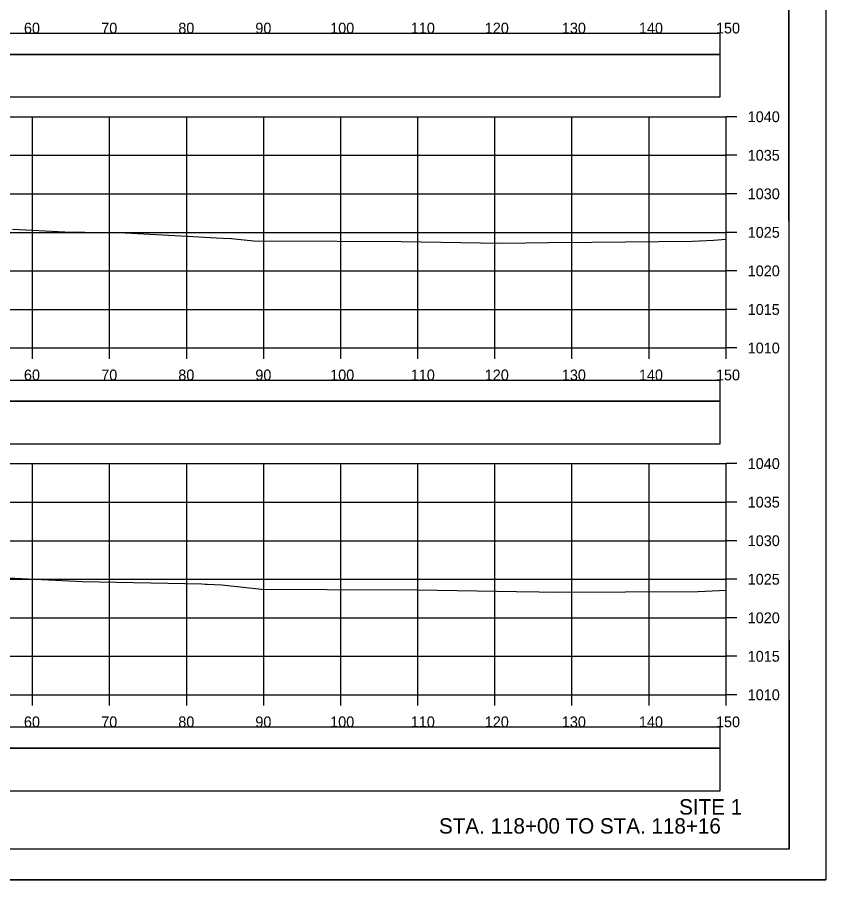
# Model space of a CAD drawing. Extents: x 1370565 to 1374448, y 301010 to 304637.
# Drawn here: x 1370793 to 1370898, y 302930.5 to 303042.4 of the extents above; entities that cross this region are included whole.
import ezdxf

# ---------------------------------------------------------------- set-up
doc = ezdxf.new("R2010")
doc.units = 0
for name, color, linetype in [('R_Axis', 7, 'Continuous'), ('R_Axis Annot', 7, 'Continuous'), ('R_Border', 7, 'Continuous'), ('R_Draft', 7, 'Continuous'), ('R_Drive', 7, 'Continuous'), ('R_Exist Surface', 7, 'Continuous'), ('R_Grid', 7, 'Continuous'), ('R_No Plot', 7, 'Continuous')]:
    doc.layers.add(name, color=color, linetype=linetype)

msp = doc.modelspace()

# ---------------------------------------------------------------- linework, layer by layer
at = {"layer": 'R_Axis'}
for p, q in [((1370885.03, 302999.52), (1370885.03, 303029.52)), ((1370886.43, 303029.52), (1370885.03, 303029.52)), ((1370886.43, 303024.52), (1370885.03, 303024.52)), ((1370886.43, 303019.52), (1370885.03, 303019.52)), ((1370886.43, 303014.52), (1370885.03, 303014.52)), ((1370886.43, 303009.52), (1370885.03, 303009.52)), ((1370886.43, 303004.52), (1370885.03, 303004.52)), ((1370585.03, 302999.52), (1370885.03, 302999.52)), ((1370795.03, 302998.12), (1370795.03, 302999.52)), ((1370805.03, 302998.12), (1370805.03, 302999.52)), ((1370815.03, 302998.12), (1370815.03, 302999.52)), ((1370825.03, 302998.12), (1370825.03, 302999.52)), ((1370835.03, 302998.12), (1370835.03, 302999.52)), ((1370845.03, 302998.12), (1370845.03, 302999.52)), ((1370855.03, 302998.12), (1370855.03, 302999.52)), ((1370865.03, 302998.12), (1370865.03, 302999.52)), ((1370875.03, 302998.12), (1370875.03, 302999.52)), ((1370885.03, 302998.12), (1370885.03, 302999.52)), ((1370886.43, 302999.52), (1370885.03, 302999.52)), ((1370885.03, 302954.52), (1370885.03, 302984.52)), ((1370886.43, 302984.52), (1370885.03, 302984.52)), ((1370886.43, 302979.52), (1370885.03, 302979.52)), ((1370886.43, 302974.52), (1370885.03, 302974.52)), ((1370886.43, 302969.52), (1370885.03, 302969.52)), ((1370886.43, 302964.52), (1370885.03, 302964.52)), ((1370886.43, 302959.52), (1370885.03, 302959.52)), ((1370585.03, 302954.52), (1370885.03, 302954.52)), ((1370795.03, 302953.12), (1370795.03, 302954.52)), ((1370805.03, 302953.12), (1370805.03, 302954.52)), ((1370815.03, 302953.12), (1370815.03, 302954.52)), ((1370825.03, 302953.12), (1370825.03, 302954.52)), ((1370835.03, 302953.12), (1370835.03, 302954.52)), ((1370845.03, 302953.12), (1370845.03, 302954.52)), ((1370855.03, 302953.12), (1370855.03, 302954.52)), ((1370865.03, 302953.12), (1370865.03, 302954.52)), ((1370875.03, 302953.12), (1370875.03, 302954.52)), ((1370885.03, 302953.12), (1370885.03, 302954.52)), ((1370886.43, 302954.52), (1370885.03, 302954.52))]:
    msp.add_line(p, q, dxfattribs=at)
at = {"layer": 'R_Border'}
for q in [(1370893.21, 303139.98), (1370577.03, 302934.52)]:
    msp.add_line((1370893.21, 302934.52), q, dxfattribs=at)
at = {"layer": 'R_Drive'}
for points in [[(1370585.82, 303037.61), (1370884.24, 303037.61), (1370884.24, 303040.32), (1370585.82, 303040.32)], [(1370585.82, 303032.09), (1370884.24, 303032.09), (1370884.24, 303037.61), (1370585.82, 303037.61)], [(1370585.82, 302992.61), (1370884.24, 302992.61), (1370884.24, 302995.32), (1370585.82, 302995.32)], [(1370585.82, 302987.09), (1370884.24, 302987.09), (1370884.24, 302992.61), (1370585.82, 302992.61)], [(1370585.82, 302947.61), (1370884.24, 302947.61), (1370884.24, 302950.32), (1370585.82, 302950.32)], [(1370585.82, 302942.09), (1370884.24, 302942.09), (1370884.24, 302947.61), (1370585.82, 302947.61)]]:
    msp.add_lwpolyline(points, close=True, dxfattribs=at)
at = {"layer": 'R_Exist Surface'}
for points in [[(1370792.42, 303014.93), (1370799.21, 303014.61), (1370807.03, 303014.45), (1370815.1, 303014.02), (1370818.85, 303013.79), (1370819.76, 303013.77), (1370820.83, 303013.73), (1370823.71, 303013.41), (1370834.56, 303013.38), (1370842.88, 303013.33), (1370855.77, 303013.11), (1370859.03, 303013.17), (1370862, 303013.22), (1370867.62, 303013.27), (1370880.67, 303013.4), (1370883.41, 303013.52), (1370885.03, 303013.65)], [(1370788.28, 302969.88), (1370801.51, 302969.24), (1370816.99, 302968.92), (1370817.44, 302968.89), (1370817.64, 302968.88), (1370817.69, 302968.88), (1370819.6, 302968.81), (1370824.73, 302968.23), (1370833.28, 302968.21), (1370845, 302968.15), (1370857.83, 302967.92), (1370860.78, 302967.9), (1370862.58, 302967.85), (1370881.36, 302967.94), (1370881.39, 302967.94), (1370885.03, 302968.11)]]:
    msp.add_lwpolyline(points, dxfattribs=at)
at = {"layer": 'R_Grid'}
for p, q in [((1370585.03, 303029.52), (1370885.03, 303029.52)), ((1370795.03, 302999.52), (1370795.03, 303029.52)), ((1370805.03, 302999.52), (1370805.03, 303029.52)), ((1370815.03, 302999.52), (1370815.03, 303029.52)), ((1370825.03, 302999.52), (1370825.03, 303029.52)), ((1370835.03, 302999.52), (1370835.03, 303029.52)), ((1370845.03, 302999.52), (1370845.03, 303029.52)), ((1370855.03, 302999.52), (1370855.03, 303029.52)), ((1370865.03, 302999.52), (1370865.03, 303029.52)), ((1370875.03, 302999.52), (1370875.03, 303029.52)), ((1370885.03, 302999.52), (1370885.03, 303029.52)), ((1370585.03, 303024.52), (1370885.03, 303024.52)), ((1370585.03, 303019.52), (1370885.03, 303019.52)), ((1370585.03, 303014.52), (1370885.03, 303014.52)), ((1370585.03, 303009.52), (1370885.03, 303009.52)), ((1370585.03, 303004.52), (1370885.03, 303004.52)), ((1370585.03, 302999.52), (1370885.03, 302999.52)), ((1370585.03, 302984.52), (1370885.03, 302984.52)), ((1370795.03, 302954.52), (1370795.03, 302984.52)), ((1370805.03, 302954.52), (1370805.03, 302984.52)), ((1370815.03, 302954.52), (1370815.03, 302984.52)), ((1370825.03, 302954.52), (1370825.03, 302984.52)), ((1370835.03, 302954.52), (1370835.03, 302984.52)), ((1370845.03, 302954.52), (1370845.03, 302984.52)), ((1370855.03, 302954.52), (1370855.03, 302984.52)), ((1370865.03, 302954.52), (1370865.03, 302984.52)), ((1370875.03, 302954.52), (1370875.03, 302984.52)), ((1370885.03, 302954.52), (1370885.03, 302984.52)), ((1370585.03, 302979.52), (1370885.03, 302979.52)), ((1370585.03, 302974.52), (1370885.03, 302974.52)), ((1370585.03, 302969.52), (1370885.03, 302969.52)), ((1370585.03, 302964.52), (1370885.03, 302964.52)), ((1370585.03, 302959.52), (1370885.03, 302959.52)), ((1370585.03, 302954.52), (1370885.03, 302954.52))]:
    msp.add_line(p, q, dxfattribs=at)
at = {"layer": 'R_No Plot'}
msp.add_line((1370564.63, 302930.54), (1370897.96, 302930.54), dxfattribs=at)
for points in [[(1370564.62, 303143.87), (1370897.96, 303143.87), (1370897.96, 302930.53), (1370564.62, 302930.53)], [(1370810.95, 303139.98), (1370830.57, 303139.98), (1370830.57, 303130.1), (1370846.68, 303130.1), (1370869.88, 303130.1), (1370869.88, 303097.43), (1370893.09, 303097.43), (1370893.21, 302934.52), (1370577.03, 302934.52), (1370577.03, 303139.98)]]:
    msp.add_lwpolyline(points, close=True, dxfattribs=at)

# ---------------------------------------------------------------- texts
at = {"layer": 'R_Axis Annot'}
for s, p in [('60', (1370793.91, 303040.32)), ('70', (1370803.94, 303040.32)), ('80', (1370813.94, 303040.32)), ('90', (1370823.94, 303040.32)), ('100', (1370833.65, 303040.32)), ('110', (1370844.11, 303040.32)), ('120', (1370853.71, 303040.32)), ('130', (1370863.71, 303040.32)), ('140', (1370873.71, 303040.32)), ('150', (1370883.71, 303040.32)), ('1040', (1370887.83, 303028.82)), ('1035', (1370887.83, 303023.82)), ('1030', (1370887.83, 303018.82)), ('1025', (1370887.83, 303013.82)), ('1020', (1370887.83, 303008.82)), ('1015', (1370887.83, 303003.82)), ('1010', (1370887.83, 302998.82)), ('60', (1370793.91, 302995.32)), ('70', (1370803.94, 302995.32)), ('80', (1370813.94, 302995.32)), ('90', (1370823.94, 302995.32)), ('100', (1370833.65, 302995.32)), ('110', (1370844.11, 302995.32)), ('120', (1370853.71, 302995.32)), ('130', (1370863.71, 302995.32)), ('140', (1370873.71, 302995.32)), ('150', (1370883.71, 302995.32)), ('1040', (1370887.83, 302983.82)), ('1035', (1370887.83, 302978.82)), ('1030', (1370887.83, 302973.82)), ('1025', (1370887.83, 302968.82)), ('1020', (1370887.83, 302963.82)), ('1015', (1370887.83, 302958.82)), ('1010', (1370887.83, 302953.82)), ('60', (1370793.91, 302950.32)), ('70', (1370803.94, 302950.32)), ('80', (1370813.94, 302950.32)), ('90', (1370823.94, 302950.32)), ('100', (1370833.65, 302950.32)), ('110', (1370844.11, 302950.32)), ('120', (1370853.71, 302950.32)), ('130', (1370863.71, 302950.32)), ('140', (1370873.71, 302950.32)), ('150', (1370883.71, 302950.32))]:
    msp.add_text(s, height=1.4, dxfattribs=at).set_placement(p)
at = {"layer": 'R_Draft'}
for s, p in [('SITE 1', (1370878.93, 302938.99)), ('STA. 118+00 TO STA. 118+16', (1370847.77, 302936.52))]:
    msp.add_text(s, height=2, dxfattribs=at).set_placement(p)

doc.saveas('drawing.dxf')
